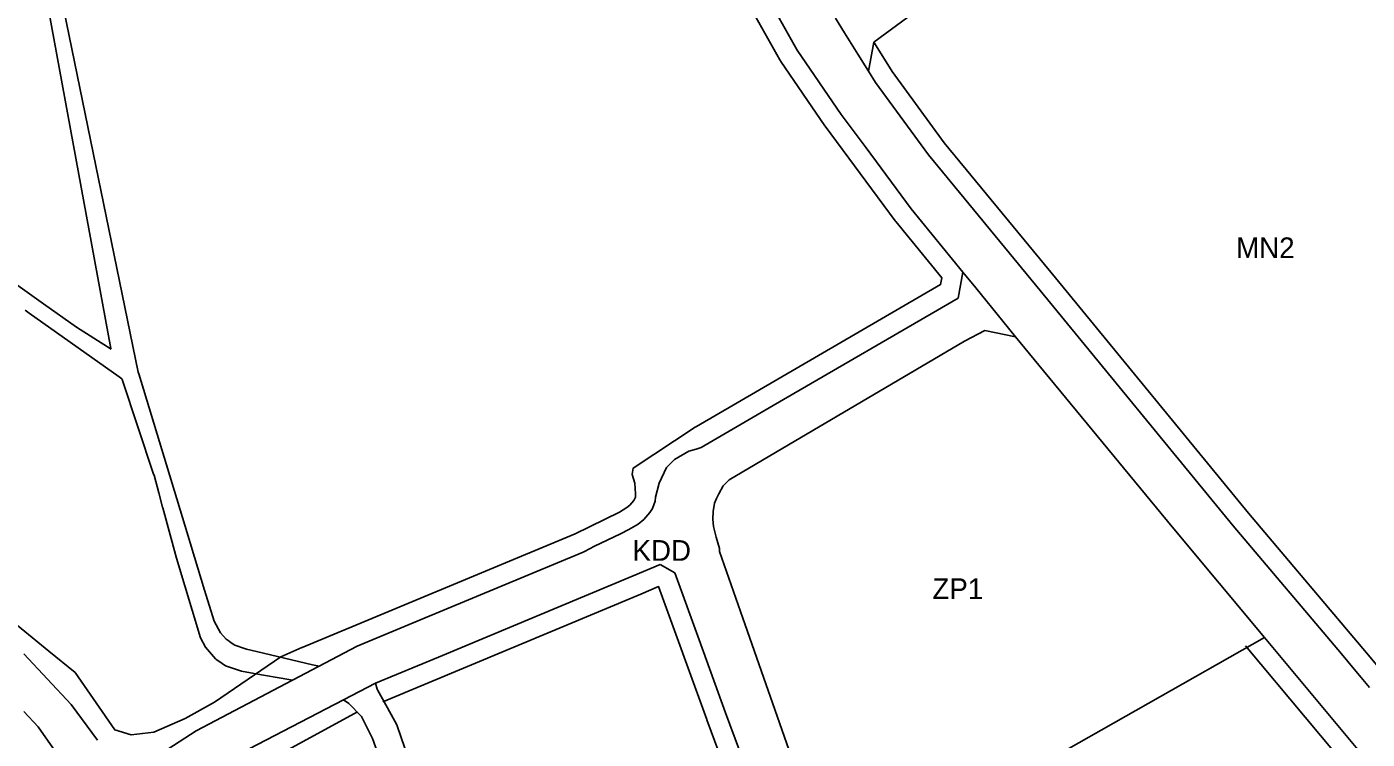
# Model space of a CAD drawing. Extents: x 7435758 to 7439981, y 5550649 to 5554049.
# Drawn here: x 7437108.2 to 7437444.8, y 5551959.4 to 5552138.3 of the extents above; entities that cross this region are included whole.
import ezdxf

# ---------------------------------------------------------------- set-up
doc = ezdxf.new("R2010")
doc.units = 0
for name, color, linetype in [('_Tereny_wyrok', 7, 'Continuous'), ('linie_rozgraniczające', 7, 'Continuous'), ('linie_zabudowy_nieprzekraczalne', 7, 'Continuous'), ('oznaczenia_przeznaczen', 7, 'Continuous')]:
    doc.layers.add(name, color=color, linetype=linetype)

msp = doc.modelspace()

# ---------------------------------------------------------------- linework, layer by layer
at = {"layer": '_Tereny_wyrok'}
for p, q in [((7437115.07, 5552154.38), (7437136.22, 5552051.57)), ((7437301.69, 5552132.42), (7437291.87, 5552149.93)), ((7437312.76, 5552116.27), (7437301.69, 5552132.42)), ((7437318.98, 5552107.87), (7437312.76, 5552116.27)), ((7437330.32, 5552092.58), (7437318.98, 5552107.87)), ((7437343.33, 5552076.64), (7437330.32, 5552092.58)), ((7437342.16, 5552070.19), (7437343.33, 5552076.64)), ((7437295.7, 5552043.19), (7437342.16, 5552070.19)), ((7437136.22, 5552051.57), (7437136.35, 5552051.15)), ((7437136.35, 5552051.15), (7437147.89, 5552013.16)), ((7437277.58, 5552032.65), (7437295.7, 5552043.19)), ((7437270.9, 5552029.62), (7437274.5, 5552031.78)), ((7437274.5, 5552031.78), (7437276.3, 5552032.26)), ((7437276.3, 5552032.26), (7437277.58, 5552032.65)), ((7437267.07, 5552023.68), (7437268.91, 5552027.62)), ((7437268.91, 5552027.62), (7437270.9, 5552029.62)), ((7437266.07, 5552020.21), (7437267.07, 5552023.68)), ((7437266.04, 5552019.16), (7437266.07, 5552020.21)), ((7437264.65, 5552016.34), (7437265.32, 5552017.31)), ((7437265.32, 5552017.31), (7437266.04, 5552019.16)), ((7437259.45, 5552012.09), (7437261.76, 5552013.45)), ((7437261.76, 5552013.45), (7437263.22, 5552014.62)), ((7437263.22, 5552014.62), (7437264.65, 5552016.34)), ((7437147.89, 5552013.16), (7437150.34, 5552005.1)), ((7437250.76, 5552007.86), (7437257.28, 5552010.98)), ((7437257.28, 5552010.98), (7437259.45, 5552012.09)), ((7437248.29, 5552006.53), (7437250.76, 5552007.86)), ((7437150.34, 5552005.1), (7437152.86, 5551996.81)), ((7437206.29, 5551989.07), (7437247.92, 5552006.38)), ((7437247.92, 5552006.38), (7437248.29, 5552006.53)), ((7437152.86, 5551996.81), (7437155.26, 5551989.05)), ((7437155.26, 5551989.05), (7437156.9, 5551986.12)), ((7437191.21, 5551982.8), (7437206.29, 5551989.07)), ((7437156.9, 5551986.12), (7437158.31, 5551984.53)), ((7437158.31, 5551984.53), (7437159.04, 5551984.02)), ((7437159.04, 5551984.02), (7437159.56, 5551983.66)), ((7437159.56, 5551983.66), (7437160.46, 5551983.04)), ((7437160.46, 5551983.04), (7437162.92, 5551982.21)), ((7437162.92, 5551982.21), (7437163.41, 5551982.05)), ((7437163.41, 5551982.05), (7437165.88, 5551981.46)), ((7437165.88, 5551981.46), (7437179.96, 5551978.13)), ((7437181.48, 5551977.69), (7437191.21, 5551982.8)), ((7437179.96, 5551978.13), (7437181.21, 5551977.83)), ((7437181.21, 5551977.83), (7437181.48, 5551977.69))]:
    msp.add_line(p, q, dxfattribs=at)
at = {"layer": 'linie_rozgraniczające'}
for p, q in [((7437104.48, 5552192.3), (7437129.36, 5552057.48)), ((7437380.16, 5552178.26), (7437320.93, 5552134.39)), ((7437136.22, 5552051.57), (7437115.07, 5552154.38)), ((7437291.87, 5552149.93), (7437301.69, 5552132.42)), ((7437313.58, 5552136.79), (7437311.29, 5552140.46)), ((7437316.93, 5552131.42), (7437313.58, 5552136.79)), ((7437301.69, 5552132.42), (7437312.76, 5552116.27)), ((7437319.6, 5552127.13), (7437316.93, 5552131.42)), ((7437320.93, 5552134.39), (7437319.6, 5552127.13)), ((7437321.38, 5552124.27), (7437319.6, 5552127.13)), ((7437334.65, 5552106.1), (7437321.38, 5552124.27)), ((7437312.76, 5552116.27), (7437318.98, 5552107.87)), ((7437318.98, 5552107.87), (7437330.32, 5552092.58)), ((7437362.72, 5552072.08), (7437334.65, 5552106.1)), ((7437330.32, 5552092.58), (7437343.33, 5552076.64)), ((7437112.44, 5552068.75), (7437099.88, 5552077.62)), ((7437343.33, 5552076.64), (7437342.16, 5552070.19)), ((7437346.52, 5552072.73), (7437343.33, 5552076.64)), ((7437353.33, 5552064.39), (7437346.52, 5552072.73)), ((7437411.17, 5552013.03), (7437362.72, 5552072.08)), ((7437120.68, 5552062.91), (7437112.44, 5552068.75)), ((7437342.16, 5552070.19), (7437295.7, 5552043.19)), ((7437107.84, 5552067.1), (7437108.81, 5552066.42)), ((7437108.81, 5552066.42), (7437131.4, 5552050.38)), ((7437356.55, 5552060.45), (7437353.33, 5552064.39)), ((7437129.38, 5552057.35), (7437120.68, 5552062.91)), ((7437343.69, 5552059.39), (7437348.84, 5552062.06)), ((7437348.84, 5552062.06), (7437356.55, 5552060.45)), ((7437129.36, 5552057.48), (7437129.38, 5552057.35)), ((7437299.49, 5552033.33), (7437343.69, 5552059.39)), ((7437356.55, 5552060.45), (7437362.34, 5552053.36)), ((7437136.35, 5552051.15), (7437136.22, 5552051.57)), ((7437147.89, 5552013.16), (7437136.35, 5552051.15)), ((7437362.34, 5552053.36), (7437395.89, 5552012.73)), ((7437131.4, 5552050.38), (7437132.1, 5552049.91)), ((7437132.1, 5552049.91), (7437132.17, 5552049.71)), ((7437132.17, 5552049.71), (7437140.08, 5552026.01)), ((7437295.7, 5552043.19), (7437277.58, 5552032.65)), ((7437274.5, 5552031.78), (7437270.9, 5552029.62)), ((7437276.3, 5552032.26), (7437274.5, 5552031.78)), ((7437277.58, 5552032.65), (7437276.3, 5552032.26)), ((7437284.61, 5552024.56), (7437299.49, 5552033.33)), ((7437268.91, 5552027.62), (7437267.07, 5552023.68)), ((7437270.9, 5552029.62), (7437268.91, 5552027.62)), ((7437140.08, 5552026.01), (7437140.19, 5552025.68)), ((7437140.19, 5552025.68), (7437141.37, 5552021.3)), ((7437267.07, 5552023.68), (7437266.07, 5552020.21)), ((7437283.12, 5552023.01), (7437284.61, 5552024.56)), ((7437141.37, 5552021.3), (7437142.34, 5552017.69)), ((7437266.07, 5552020.21), (7437266.04, 5552019.16)), ((7437281.43, 5552019.86), (7437282.01, 5552021.07)), ((7437282.01, 5552021.07), (7437283.12, 5552023.01)), ((7437142.34, 5552017.69), (7437142.38, 5552017.52)), ((7437142.38, 5552017.52), (7437145.78, 5552004.91)), ((7437265.32, 5552017.31), (7437264.65, 5552016.34)), ((7437266.04, 5552019.16), (7437265.32, 5552017.31)), ((7437280.61, 5552016.59), (7437280.93, 5552018.66)), ((7437280.93, 5552018.66), (7437281.43, 5552019.86)), ((7437261.76, 5552013.45), (7437259.45, 5552012.09)), ((7437263.22, 5552014.62), (7437261.76, 5552013.45)), ((7437264.65, 5552016.34), (7437263.22, 5552014.62)), ((7437280.53, 5552014.69), (7437280.61, 5552016.59)), ((7437280.69, 5552012.8), (7437280.53, 5552014.69)), ((7437150.34, 5552005.1), (7437147.89, 5552013.16)), ((7437257.28, 5552010.98), (7437250.76, 5552007.86)), ((7437259.45, 5552012.09), (7437257.28, 5552010.98)), ((7437281.35, 5552010.13), (7437280.69, 5552012.8)), ((7437282.18, 5552007.32), (7437281.35, 5552010.13)), ((7437395.89, 5552012.73), (7437419.08, 5551984.95)), ((7437438.35, 5551980.83), (7437411.17, 5552013.03)), ((7437250.76, 5552007.86), (7437248.29, 5552006.53)), ((7437282.21, 5552006.54), (7437282.18, 5552007.32)), ((7437145.78, 5552004.91), (7437151.85, 5551984.9)), ((7437152.86, 5551996.81), (7437150.34, 5552005.1)), ((7437247.92, 5552006.38), (7437206.29, 5551989.07)), ((7437248.29, 5552006.53), (7437247.92, 5552006.38)), ((7437260.48, 5552000.45), (7437267.25, 5552003.32)), ((7437267.25, 5552003.32), (7437270.95, 5552001.21)), ((7437288.06, 5551989.83), (7437282.21, 5552006.54)), ((7437211.61, 5551980.06), (7437260.48, 5552000.45)), ((7437270.95, 5552001.21), (7437277.04, 5551984.37)), ((7437155.26, 5551989.05), (7437152.86, 5551996.81)), ((7437310.72, 5551925.14), (7437288.06, 5551989.83)), ((7437156.9, 5551986.12), (7437155.26, 5551989.05)), ((7437206.29, 5551989.07), (7437191.21, 5551982.8)), ((7437151.85, 5551984.9), (7437153.07, 5551982.52)), ((7437158.31, 5551984.53), (7437156.9, 5551986.12)), ((7437159.04, 5551984.02), (7437158.31, 5551984.53)), ((7437159.56, 5551983.66), (7437159.04, 5551984.02)), ((7437160.46, 5551983.04), (7437159.56, 5551983.66)), ((7437277.04, 5551984.37), (7437283.67, 5551966.04)), ((7437311.16, 5551923.91), (7437419.08, 5551984.95)), ((7437419.08, 5551984.95), (7437448.05, 5551950.24)), ((7437119.37, 5551968.13), (7437107.51, 5551980.83)), ((7437153.07, 5551982.52), (7437155.6, 5551979.57)), ((7437162.92, 5551982.21), (7437160.46, 5551983.04)), ((7437163.41, 5551982.05), (7437162.92, 5551982.21)), ((7437165.88, 5551981.46), (7437163.41, 5551982.05)), ((7437179.96, 5551978.13), (7437165.88, 5551981.46)), ((7437191.21, 5551982.8), (7437181.48, 5551977.69)), ((7437195.83, 5551973.47), (7437211.61, 5551980.06)), ((7437441.54, 5551977.04), (7437438.35, 5551980.83)), ((7437155.6, 5551979.57), (7437155.79, 5551979.44)), ((7437155.79, 5551979.44), (7437156.44, 5551978.99)), ((7437156.44, 5551978.99), (7437158.12, 5551977.82)), ((7437158.12, 5551977.82), (7437162.17, 5551976.49)), ((7437162.17, 5551976.49), (7437167.19, 5551975.61)), ((7437174.92, 5551974.25), (7437181.48, 5551977.69)), ((7437181.21, 5551977.83), (7437179.96, 5551978.13)), ((7437181.48, 5551977.69), (7437181.21, 5551977.83)), ((7437443.31, 5551974.95), (7437441.54, 5551977.04)), ((7437174.92, 5551974.25), (7437150.73, 5551961.56)), ((7437167.19, 5551975.61), (7437172.12, 5551974.75)), ((7437172.12, 5551974.75), (7437174.92, 5551974.25)), ((7437195.81, 5551973.47), (7437187.73, 5551969.28)), ((7437196.25, 5551971.97), (7437195.81, 5551973.47)), ((7437195.81, 5551973.47), (7437195.83, 5551973.47)), ((7437445.45, 5551972.38), (7437443.31, 5551974.95)), ((7437196.32, 5551971.85), (7437196.25, 5551971.97)), ((7437198.8, 5551967.32), (7437196.32, 5551971.85)), ((7437107.45, 5551966.38), (7437111.09, 5551962.57)), ((7437125.96, 5551959.19), (7437119.37, 5551968.13)), ((7437155.38, 5551952.51), (7437187.73, 5551969.28)), ((7437187.73, 5551969.28), (7437189.1, 5551968.43)), ((7437189.1, 5551968.43), (7437192.25, 5551965.11)), ((7437201.15, 5551963.03), (7437198.8, 5551967.32)), ((7437192.25, 5551965.11), (7437195.02, 5551959.58)), ((7437201.22, 5551962.82), (7437201.15, 5551963.03)), ((7437283.67, 5551966.04), (7437287.17, 5551956.64)), ((7437111.09, 5551962.57), (7437117.68, 5551953.08)), ((7437150.73, 5551961.56), (7437137.72, 5551953.08)), ((7437195.02, 5551959.58), (7437196.99, 5551954.22)), ((7437213.75, 5551926.75), (7437201.22, 5551962.82))]:
    msp.add_line(p, q, dxfattribs=at)
at = {"layer": 'linie_zabudowy_nieprzekraczalne'}
for points in [[(7437099.78, 5551992.9), (7437113.79, 5551981.52), (7437120.4, 5551976.14), (7437125.63, 5551968.56), (7437130.33, 5551961.75), (7437134.43, 5551960.53), (7437140.14, 5551961.23), (7437147.97, 5551964.67), (7437155.36, 5551968.73), (7437171.99, 5551980.14), (7437177.31, 5551982.44), (7437177.37, 5551982.46), (7437245.97, 5552010.98), (7437257.04, 5552016.47), (7437258.92, 5552017.58), (7437259.7, 5552018.2), (7437260.66, 5552019.36), (7437261.08, 5552020.19), (7437261.11, 5552021.02), (7437260.93, 5552023.67), (7437260.26, 5552025.88), (7437260.28, 5552026.01), (7437260.51, 5552027.49), (7437276.09, 5552037.73), (7437276.44, 5552037.96), (7437337.69, 5552073.56), (7437338, 5552075.27), (7437326.45, 5552089.41), (7437326.3, 5552089.6), (7437308.74, 5552113.3), (7437308.72, 5552113.33), (7437308.63, 5552113.45), (7437297.56, 5552129.6), (7437297.46, 5552129.75), (7437297.33, 5552129.98), (7437287.5, 5552147.48)], [(7437320.93, 5552134.39), (7437324.87, 5552128.13), (7437325.53, 5552127.07), (7437338.6, 5552109.16), (7437366.58, 5552075.27), (7437366.59, 5552075.26), (7437415.01, 5552016.22), (7437445.57, 5551979.99), (7437450.09, 5551974.62), (7437491.45, 5551925.11)], [(7437327.25, 5551677.18), (7437328.56, 5551675.97), (7437328.36, 5551687.67), (7437328.36, 5551687.78), (7437328.66, 5551749.73), (7437328.02, 5551782.17), (7437328.02, 5551782.39), (7437328.03, 5551782.45), (7437329.33, 5551819.31), (7437328.28, 5551829.75), (7437325.32, 5551839.64), (7437310.51, 5551880.32), (7437291.66, 5551930.23), (7437291.66, 5551930.26), (7437278.98, 5551964.3), (7437278.97, 5551964.34), (7437266.89, 5551997.74), (7437262.43, 5551995.85), (7437262.4, 5551995.84), (7437197.61, 5551968.8)], [(7437444.22, 5551947.04), (7437414.28, 5551982.9)], [(7437191.25, 5551966.29), (7437163.85, 5551951.36)]]:
    msp.add_lwpolyline(points, dxfattribs=at)

# ---------------------------------------------------------------- texts
at = {"layer": 'oznaczenia_przeznaczen'}
for s, p in [('MN2', (7437411.92, 5552080.2)), ('KDD', (7437260.34, 5552004.22)), ('ZP1', (7437335.65, 5551994.61))]:
    msp.add_text(s, height=5.2, dxfattribs=at).set_placement(p)

doc.saveas('drawing.dxf')
